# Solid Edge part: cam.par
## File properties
Author: Deepak Maini
Template: normal.par
Last saved by: CADCIM
Revision: 3
Application: Solid Edge
Accuracy: 0.99
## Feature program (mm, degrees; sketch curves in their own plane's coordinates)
sketch for "unnamed Protrusion 1" plane through (0, 0, 0) normal (0, -1, 0) x-axis (1, 0, 0)
  line (-48.7213, 38.3333) -> (-48.7213, 0)
  line (-48.7213, 0) -> (73.8435, 0)
  line (73.8435, 0) -> (73.8435, -9.0712)
  line (73.8435, -9.0712) -> (-55.4516, -9.0712)
  line (-55.4516, -9.0712) -> (-55.4516, 38.3333)
  line (-55.4516, 38.3333) -> (-48.7213, 38.3333)
extrude "unnamed Protrusion 1" add finite 37.8 along -normal
sketch for "ExtrudedCutout_1" plane through (-48.7213, 18.9, 19.1666) normal (1, 0, 0) x-axis (0, 1, 0)
  line (-5.0674, -0.2952) -> (-5.0674, 8.2652)
  line (-5.0674, 8.2652) -> (3.6898, 8.2652)
  line (3.6898, 8.2652) -> (3.6898, -0.2952)
  line (3.6898, -0.2952) -> (-5.0674, -0.2952)
extrude "ExtrudedCutout_1" cut finite 123.95 along -normal
sketch for "Hole_1" plane through (12.5611, 18.9, 0) normal (0, 0, 1) x-axis (0, 1, 0)
  hole centre (0.7865, -41.5278) bore radius 3.5
hole "Hole_1" diameter 7 through
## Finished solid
Body 1: solid body, 13 faces, 32 edges, 20 vertices.
  Faces by surface: plane 12, cylinder 1
  Edges by curve: line 30, circle 2
Bounding box of the edges (mm): 129.295 x 37.800 x 47.404, from (-55.4516, 0, -9.0712) to (73.8435, 37.8, 38.3333).
Cylindrical faces by radius (mm): R3.5 x1
Planar faces by outward normal: +x 2, +y 2, +z 3, -x 1, -y 2, -z 2
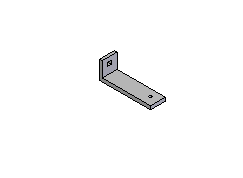
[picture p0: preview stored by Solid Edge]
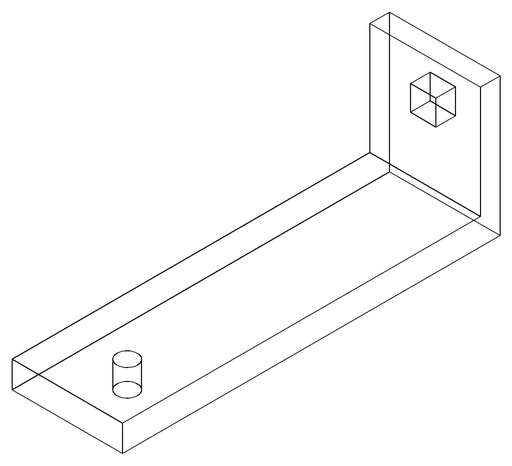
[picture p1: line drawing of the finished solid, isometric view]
